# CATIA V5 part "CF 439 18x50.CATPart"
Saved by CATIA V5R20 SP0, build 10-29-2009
Part number: CF 439 18x50
Definition: NONE
Nomenclature: CF 439 18x50
Source: Unknown
Description: CF 439 18x50
Bounding box of the stored display mesh (mm): x -17 to 17, y 0 to 50, z -17 to 17
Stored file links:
  C:\Users\Utente\Desktop\IO LAVORO\3D X SITO CF\X SITO\CF 439\CF 439 18x50.CATPart
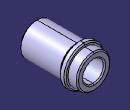
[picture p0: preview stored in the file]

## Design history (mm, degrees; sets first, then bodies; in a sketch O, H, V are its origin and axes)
Body1 "CF 439 18x50" (main body)
  Solid1: solid without history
